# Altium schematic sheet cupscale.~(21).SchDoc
size A
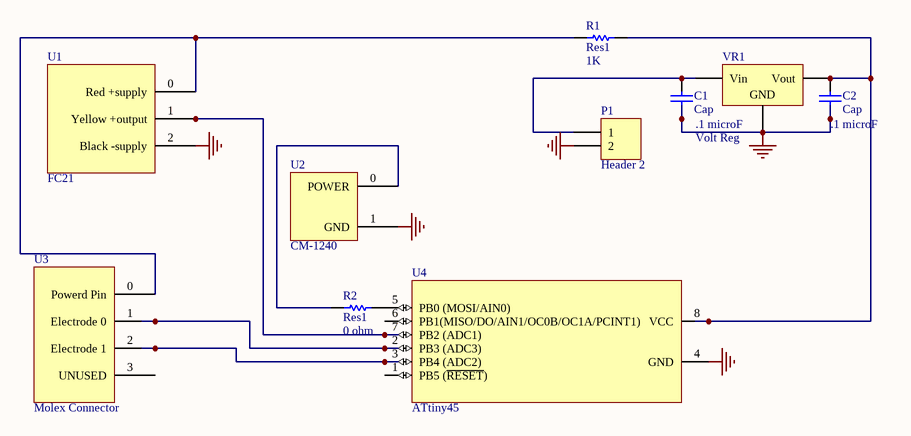
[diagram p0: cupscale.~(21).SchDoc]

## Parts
C1  Cap  value .1 microF  [3216[1206]]
C2  Cap  value .1 microF  [3216[1206]]
P1  Header 2  [HDR1X2]
R1  Res1  value 1K  [3216[1206]]
R2  Res1  value 0 ohm  [3216[1206]]
U1  FC21  [FC21-Load Cell]
U2  CM-1240  [CMI-1240-buzzer]
U3  Molex Connector  [4 PIN Molex]
U4  ATtiny45  [8S2_M]
VR1  Volt Reg  [SOT-23]

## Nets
GND: C1.1 C2.1 P1.2 U1.2(Black_-supply) U2.1(GND) U4.4(GND) VR1.3(GND)
NetC1_2: C1.2 P1.1 VR1.2(Vin)
NetC2_2: C2.2 R1.2 U4.8(VCC) VR1.1(Vout)
NetR1_1: R1.1 U1.0(Red_+supply) U3.0(Powerd_Pin)
NetR2_1: R2.1 U2.0(POWER)
NetR2_2: R2.2 U4.5(PB0_(MOSI/AIN0))
NetU1_1: U1.1(Yellow_+output) U4.7(PB2_(ADC1))
NetU3_1: U3.1(Electrode_0) U4.2(PB3_(ADC3))
NetU3_2: U3.2(Electrode_1) U4.3(PB4_(ADC2))

Not connected (* = marked no-connect by the designer): U3 3(UNUSED); U4 1(PB5_(~{RESET})) 6(PB1(MISO/DO/AIN1/OC0B/OC1A/PCINT1))

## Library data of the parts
C1 C2 = Cap: Capacitor
P1 = Header 2: Header, 2-Pin
R1 R2 = Res1: Resistor
U2 = CMI-1240
U4 = ATtiny45: 8-Bit AVR Microcontroller with 1K Byte of Flash Memory
VR1 = Volt Reg: Voltage Regulator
